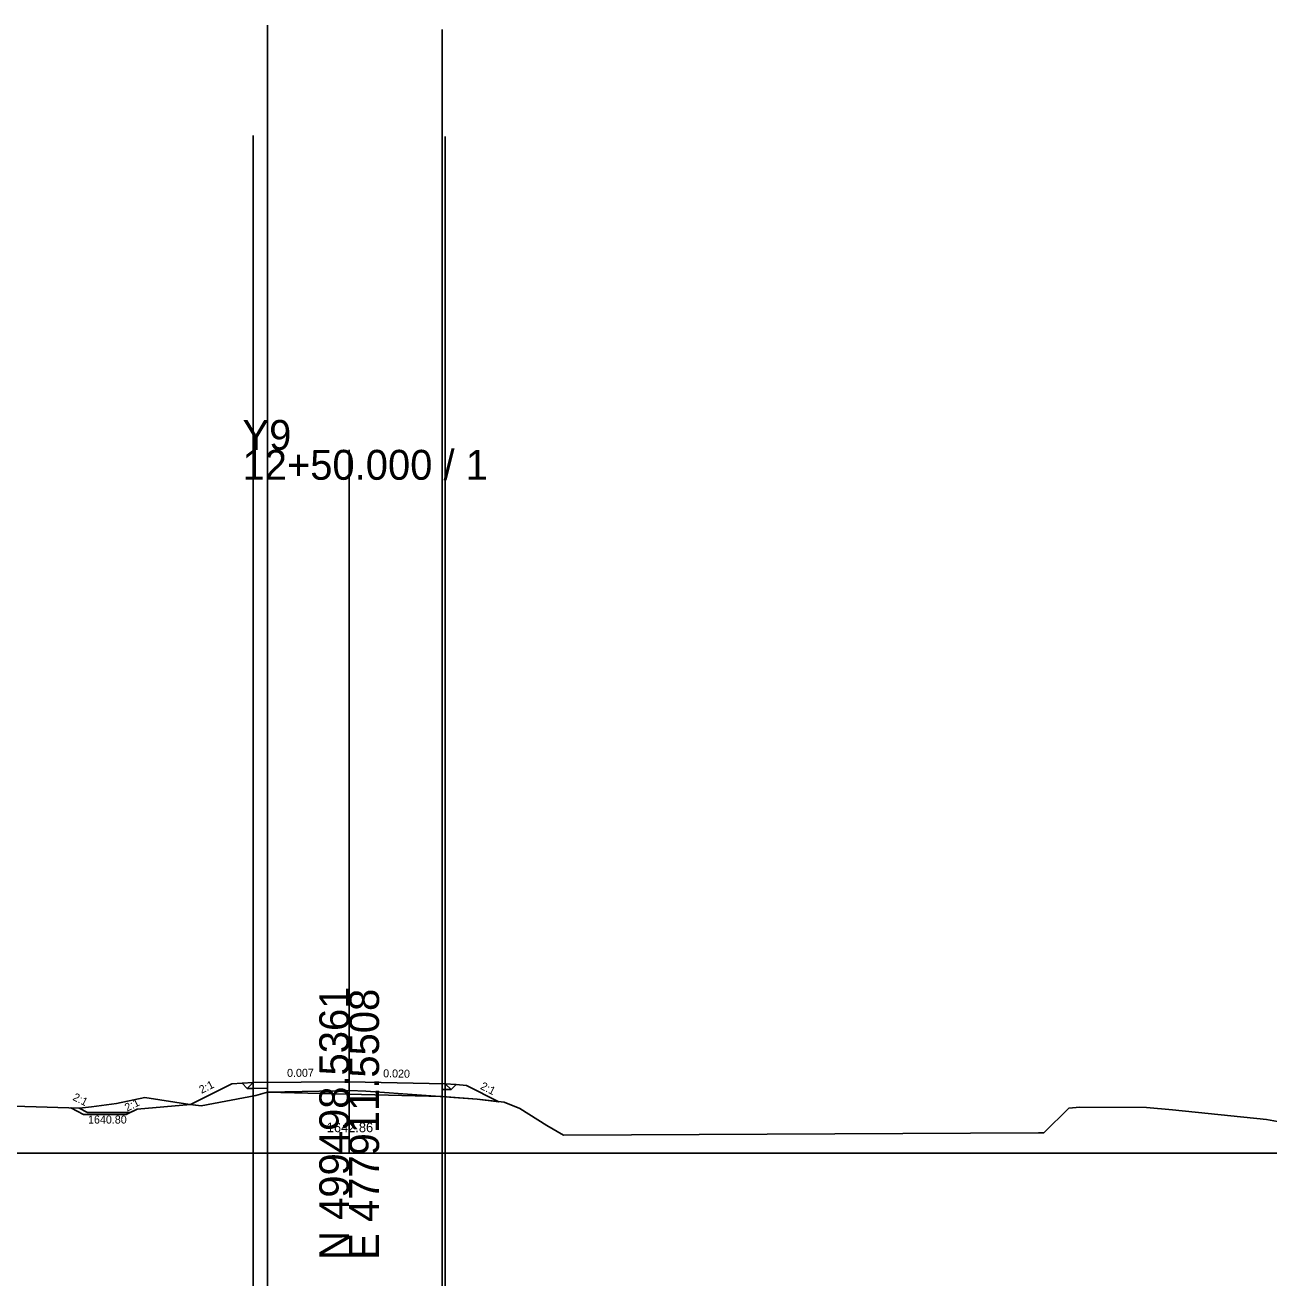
# Model space of a CAD drawing. Extents: x -26 to 403, y -99 to 4540.
# Drawn here: x 169.6 to 286.2, y 2488.3 to 2605.7 of the extents above; entities that cross this region are included whole.
import ezdxf

# ---------------------------------------------------------------- set-up
doc = ezdxf.new("R2010")
doc.units = 0
for name, color, linetype in [('Exist Cross Section Cell', 7, 'Continuous'), ('Exist XS Center Line Elevation Label', 7, 'Continuous'), ('Exist XS Ground Line', 7, 'Continuous'), ('Prop XS DDE', 7, 'Continuous'), ('Prop XS DDE Earthwork Shape', 7, 'Continuous'), ('Prop XS Ditch Slope Text', 7, 'Continuous'), ('Prop XS Ditch Standard Text', 7, 'Continuous'), ('Prop XS Dump Level', 7, 'Continuous'), ('Prop XS Earthwork Shape', 7, 'Continuous'), ('Prop XS EOT Tick Mark', 7, 'Continuous'), ('Prop XS Finish Grade', 7, 'Continuous'), ('Prop XS Finish Grade Earthwork', 7, 'Continuous'), ('Prop XS Finish Grade Pavement', 7, 'Continuous'), ('Prop XS Hydro Typical Ditch Data', 7, 'Continuous'), ('Prop XS Pvmt Edge Slope', 7, 'Continuous'), ('Prop XS SE Text', 7, 'Continuous'), ('Prop XS Shoulder Borrow Shape', 7, 'Continuous'), ('Prop XS Side Slope Text', 7, 'Continuous'), ('Prop XS Subgrade Earthwork', 7, 'Continuous'), ('Scratch_Level_1', 7, 'Continuous'), ('Scratch_Level_6', 7, 'Continuous')]:
    doc.layers.add(name, color=color, linetype=linetype)

msp = doc.modelspace()

# ---------------------------------------------------------------- linework, layer by layer
at = {"layer": 'Exist Cross Section Cell'}
for p, q in [((200, 2500), (200, 2565.9)), ((0, 2500), (200, 2500)), ((200, 2500), (400, 2500))]:
    msp.add_line(p, q, dxfattribs=at)
at = {"layer": 'Exist XS Ground Line'}
msp.add_lwpolyline([(166.45, 2504.46), (171.7, 2504.3), (174.73, 2504.2), (175.83, 2504.34), (178.19, 2504.66), (180.85, 2505.21), (185.05, 2504.56), (186.12, 2504.44), (191.26, 2505.41), (192.33, 2505.71), (198.84, 2505.85), (200.03, 2505.87), (201.55, 2505.82), (211.99, 2505.05), (214.53, 2504.76), (216, 2504.17), (218.52, 2502.59), (220.08, 2501.69), (264.61, 2501.91), (265.13, 2501.91), (267.47, 2504.2), (268.5, 2504.3), (274.74, 2504.27), (277.19, 2504.05), (285.99, 2503.15), (290.11, 2502.41)], dxfattribs=at)
at = {"layer": 'Prop XS DDE'}
for p, q in [((180.14, 2504.13), (185.14, 2504.55)), ((174.68, 2504.2), (175.47, 2503.8)), ((179.47, 2503.8), (175.47, 2503.8)), ((179.47, 2503.8), (180.14, 2504.13))]:
    msp.add_line(p, q, dxfattribs=at)
at = {"layer": 'Prop XS DDE Earthwork Shape'}
for p, q in [((180.14, 2504.13), (185.14, 2504.55)), ((185.14, 2504.55), (185.05, 2504.56)), ((173.9, 2504.23), (175.11, 2503.62)), ((175.11, 2503.62), (179.11, 2503.62)), ((179.11, 2503.62), (180.14, 2504.13))]:
    msp.add_line(p, q, dxfattribs=at)
msp.add_lwpolyline([(185.05, 2504.56), (180.85, 2505.21), (178.19, 2504.66), (175.83, 2504.34), (174.73, 2504.2), (173.9, 2504.23)], dxfattribs=at)
at = {"layer": 'Prop XS Dump Level'}
for p, q in [((191, 2506.61), (200, 2506.68)), ((200, 2506.68), (208.99, 2506.5))]:
    msp.add_line(p, q, dxfattribs=at)
at = {"layer": 'Prop XS Earthwork Shape'}
for points in [[(186.12, 2504.44), (191.26, 2505.41), (192.33, 2505.71), (192.33, 2506.08), (191, 2506.07), (190.45, 2506.07), (189.98, 2506.54), (189, 2506.48), (185.14, 2504.55)], [(208.71, 2505.29), (211.99, 2505.05), (214.04, 2504.82), (210.99, 2506.34), (210.02, 2506.42), (209.55, 2505.95), (208.99, 2505.96), (208.71, 2505.96)]]:
    msp.add_lwpolyline(points, close=True, dxfattribs=at)
at = {"layer": 'Prop XS EOT Tick Mark'}
for p, q in [((191, 2506.61), (191, 2507.61)), ((208.99, 2506.5), (208.99, 2507.5))]:
    msp.add_line(p, q, dxfattribs=at)
at = {"layer": 'Prop XS Finish Grade'}
for p, q in [((191, 2506.61), (189.98, 2506.54)), ((208.99, 2506.5), (210.02, 2506.42))]:
    msp.add_line(p, q, dxfattribs=at)
at = {"layer": 'Prop XS Finish Grade Earthwork'}
for p, q in [((189, 2506.48), (185.14, 2504.55)), ((189.98, 2506.54), (189, 2506.48)), ((210.02, 2506.42), (210.99, 2506.34)), ((210.99, 2506.34), (214.04, 2504.82))]:
    msp.add_line(p, q, dxfattribs=at)
at = {"layer": 'Prop XS Finish Grade Pavement'}
for p, q in [((191, 2506.61), (200, 2506.68)), ((200, 2506.68), (208.99, 2506.5))]:
    msp.add_line(p, q, dxfattribs=at)
at = {"layer": 'Prop XS Hydro Typical Ditch Data'}
msp.add_line((189, 2506.48), (185.14, 2504.55), dxfattribs=at)
at = {"layer": 'Prop XS Pvmt Edge Slope'}
for p, q in [((191, 2506.61), (190.45, 2506.07)), ((208.99, 2506.5), (209.55, 2505.95))]:
    msp.add_line(p, q, dxfattribs=at)
at = {"layer": 'Prop XS Shoulder Borrow Shape'}
for points in [[(191, 2506.61), (189.98, 2506.54), (190.45, 2506.07)], [(209.55, 2505.95), (210.02, 2506.42), (208.99, 2506.5)]]:
    msp.add_lwpolyline(points, close=True, dxfattribs=at)
at = {"layer": 'Prop XS Subgrade Earthwork'}
for p, q in [((190.45, 2506.07), (189.98, 2506.54)), ((191, 2506.07), (190.45, 2506.07)), ((192.33, 2506.08), (191, 2506.07)), ((192.33, 2506.08), (192.33, 2505.71)), ((208.99, 2505.96), (208.71, 2505.96)), ((208.71, 2505.96), (208.71, 2505.29)), ((208.99, 2505.96), (209.55, 2505.95)), ((209.55, 2505.95), (210.02, 2506.42))]:
    msp.add_line(p, q, dxfattribs=at)
at = {"layer": 'Scratch_Level_1'}
for p, q in [((192.33, 2605.71), (192.33, 2405.71)), ((208.71, 2605.29), (208.71, 2405.29))]:
    msp.add_line(p, q, dxfattribs=at)
at = {"layer": 'Scratch_Level_6'}
for p, q in [((191, 2595.36), (191, 2445.36)), ((209, 2595.27), (209, 2445.27)), ((192.33, 2505.71), (208.71, 2505.29))]:
    msp.add_line(p, q, dxfattribs=at)

# ---------------------------------------------------------------- texts
at = {"layer": 'Exist Cross Section Cell'}
for s, p in [('Y9', (190, 2565.9)), ('12+50.000 / 1', (190, 2563.1))]:
    msp.add_text(s, height=2.8, dxfattribs=at).set_placement(p)
for s, p in [('N 499498.5361', (200, 2490)), ('E 477911.5508', (202.8, 2490))]:
    msp.add_text(s, height=2.8, rotation=90, dxfattribs=at).set_placement(p)
at = {"layer": 'Exist XS Center Line Elevation Label'}
msp.add_text('1642.86', height=0.9, dxfattribs=at).set_placement((197.9, 2501.96))
at = {"layer": 'Prop XS Ditch Slope Text'}
for p in [(186.16, 2505.55), (179.18, 2503.88)]:
    msp.add_text('2:1', height=0.75, rotation=26.5651, dxfattribs=at).set_placement(p)
at = {"layer": 'Prop XS Ditch Standard Text'}
msp.add_text('1640.80', height=0.75, dxfattribs=at).set_placement((175.52, 2502.77))
at = {"layer": 'Prop XS Dump Level'}
for p in [(189, 2506.44), (210.99, 2506.3)]:
    msp.add_text('Case1', height=0.04, dxfattribs=at).set_placement(p)
at = {"layer": 'Prop XS SE Text'}
for s, rotation, p in [('0.007', 0.4095, (194.18, 2507.14)), ('0.020', 358.8542, (203.18, 2507.11))]:
    msp.add_text(s, height=0.75, rotation=rotation, dxfattribs=at).set_placement(p)
at = {"layer": 'Prop XS Side Slope Text'}
for rotation, p in [(333.4349, (212.23, 2506.04)), (333.416, (174.02, 2505.01))]:
    msp.add_text('2:1', height=0.75, rotation=rotation, dxfattribs=at).set_placement(p)

doc.saveas('drawing.dxf')
